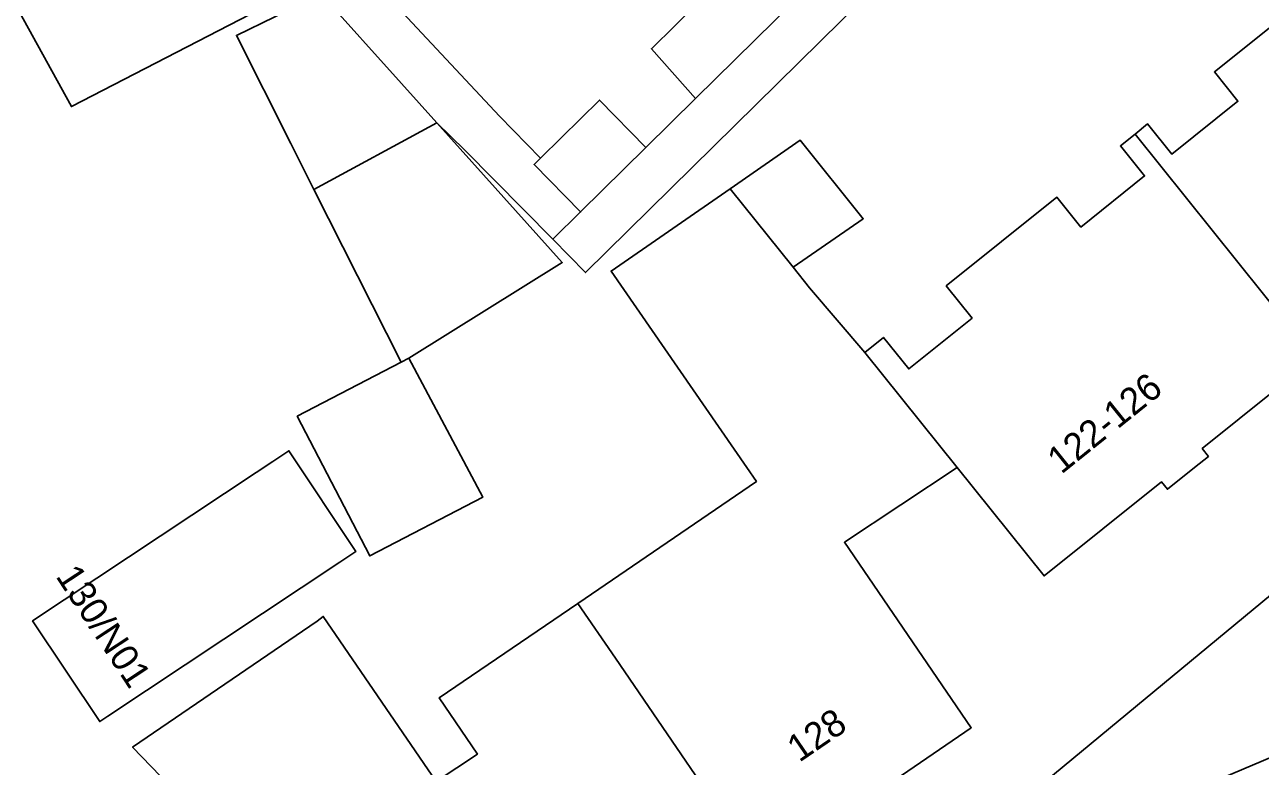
# Model space of a CAD drawing. Extents: x 161881 to 162523, y 381678 to 382381.
# Drawn here: x 162346.39 to 162392.21, y 381738.92 to 381766.42 of the extents above; entities that cross this region are included whole.
import ezdxf

# ---------------------------------------------------------------- set-up
doc = ezdxf.new("R2010")
doc.units = 0
for name, color, linetype in [('IMGEO_Erf', 7, 'Continuous'), ('IMGEO_Fietspad_gesloten', 7, 'Continuous'), ('IMGEO_Pand', 7, 'Continuous'), ('IMGEO_Pand_nummerreeks', 7, 'Continuous'), ('IMGEO_Voetpad_open', 7, 'Continuous')]:
    doc.layers.add(name, color=color, linetype=linetype)

msp = doc.modelspace()

# ---------------------------------------------------------------- linework, layer by layer
at = {"layer": 'IMGEO_Erf'}
for points in [[(162343.866, 381713.286), (162356.915, 381719.329), (162365.839, 381723.151), (162398.308, 381750), (162437.038, 381782.026)], [(162355.536, 381772.071), (162363.995, 381763.033), (162365.51, 381761.465), (162366.295, 381762.239), (162367.697, 381763.622), (162369.425, 381761.869), (162371.265, 381763.684), (162369.629, 381765.527), (162374.022, 381769.859)], [(162381.418, 381771.264), (162367.187, 381757.231), (162365.972, 381758.464), (162362.713, 381761.769), (162361.669, 381762.781), (162366.323, 381757.6), (162360.635, 381754.053), (162363.375, 381748.9), (162359.18, 381746.721), (162356.49, 381751.901), (162360.342, 381753.901), (162357.113, 381760.311), (162356.254, 381762.016), (162354.236, 381766.022), (162357.084, 381767.419)], [(162356.7, 381767.828), (162348.117, 381763.384), (162345.256, 381768.578)], [(162352.114, 381737.844), (162350.389, 381739.631), (162357.234, 381744.31), (162357.459, 381744.482), (162361.646, 381738.357), (162363.177, 381739.379), (162361.754, 381741.46), (162366.899, 381744.958), (162373.521, 381749.484), (162373.164, 381750), (162368.13, 381757.284), (162372.542, 381760.336), (162375.144, 381762.136), (162377.48, 381759.226), (162374.878, 381757.426), (162375.487, 381756.667), (162377.539, 381754.267), (162378.231, 381754.823), (162379.168, 381753.657), (162381.517, 381755.543), (162380.562, 381756.732), (162384.662, 381760.024), (162385.553, 381758.916), (162387.913, 381760.811), (162387.017, 381761.926), (162387.561, 381762.363), (162388.029, 381762.739), (162388.931, 381761.615), (162391.38, 381763.581), (162390.507, 381764.668), (162394.626, 381767.976)], [(162394.235, 381754.059), (162390.053, 381750.701), (162390.283, 381750.415), (162389.766, 381750), (162388.764, 381749.195), (162388.539, 381749.476), (162384.189, 381745.983), (162380.965, 381750), (162376.785, 381747.233), (162381.487, 381740.355), (162373.695, 381735.029)]]:
    msp.add_lwpolyline(points, dxfattribs=at)
msp.add_lwpolyline([(162358.664, 381746.886), (162358.069, 381746.491), (162349.473, 381740.786), (162349.167, 381740.583), (162346.677, 381744.311), (162354.964, 381749.81), (162355.59, 381750.226), (162356.111, 381750.571), (162356.185, 381750.621)], close=True, dxfattribs=at)
at = {"layer": 'IMGEO_Fietspad_gesloten'}
msp.add_lwpolyline([(162465.9, 381797.559), (162465.667, 381797.275), (162465.384, 381797.056), (162418.283, 381759.605), (162412.351, 381754.828), (162394.327, 381740.001), (162393.522, 381739.663), (162393.372, 381739.584), (162390.461, 381738.351), (162389.601, 381737.634), (162386.818, 381735.309), (162385.622, 381734.309), (162387.138, 381732.433), (162387.312, 381732.575), (162387.443, 381732.645), (162396.519, 381738.21), (162396.799, 381738.137), (162413.971, 381752.357), (162472.336, 381798.789)], dxfattribs=at)
at = {"layer": 'IMGEO_Pand'}
for points in [[(162356.7, 381767.828), (162352.533, 381772.272), (162345.256, 381768.578), (162348.117, 381763.384)], [(162404.147, 381762.016), (162397.503, 381770.285), (162397.027, 381769.903), (162397.869, 381768.855), (162395.468, 381766.928), (162394.626, 381767.976), (162390.507, 381764.668), (162391.38, 381763.581), (162388.931, 381761.615), (162388.029, 381762.739), (162387.561, 381762.363), (162394.235, 381754.059), (162398.417, 381757.417), (162398.654, 381757.121), (162400.207, 381758.367), (162399.97, 381758.662)], [(162369.629, 381765.527), (162371.265, 381763.684), (162375.677, 381768.034), (162374.022, 381769.859)], [(162360.358, 381764.241), (162357.375, 381767.562), (162357.084, 381767.419), (162354.236, 381766.022), (162356.254, 381762.016), (162357.113, 381760.311), (162361.669, 381762.781)], [(162367.697, 381763.622), (162366.295, 381762.239), (162365.51, 381761.465), (162365.275, 381761.233), (162367.003, 381759.48), (162369.425, 381761.869)], [(162361.669, 381762.781), (162357.113, 381760.311), (162360.342, 381753.901), (162360.635, 381754.053), (162366.323, 381757.6)], [(162372.542, 381760.336), (162374.878, 381757.426), (162377.48, 381759.226), (162375.144, 381762.136)], [(162377.539, 381754.267), (162380.965, 381750), (162384.189, 381745.983), (162388.539, 381749.476), (162388.764, 381749.195), (162389.766, 381750), (162390.283, 381750.415), (162390.053, 381750.701), (162394.235, 381754.059), (162387.561, 381762.363), (162387.017, 381761.926), (162387.913, 381760.811), (162385.553, 381758.916), (162384.662, 381760.024), (162380.562, 381756.732), (162381.517, 381755.543), (162379.168, 381753.657), (162378.231, 381754.823)], [(162380.965, 381750), (162377.539, 381754.267), (162375.487, 381756.667), (162374.878, 381757.426), (162372.542, 381760.336), (162368.13, 381757.284), (162373.164, 381750), (162373.521, 381749.484), (162366.899, 381744.958), (162368.297, 381742.927), (162373.695, 381735.029), (162381.487, 381740.355), (162376.785, 381747.233)], [(162360.635, 381754.053), (162360.342, 381753.901), (162356.49, 381751.901), (162359.18, 381746.721), (162363.375, 381748.9)], [(162346.677, 381744.311), (162349.167, 381740.583), (162349.473, 381740.786), (162358.069, 381746.491), (162358.664, 381746.886), (162356.185, 381750.621), (162356.111, 381750.571), (162355.59, 381750.226), (162354.964, 381749.81)], [(162368.297, 381742.927), (162366.899, 381744.958), (162361.754, 381741.46), (162363.177, 381739.379), (162361.646, 381738.357), (162357.459, 381744.482), (162357.234, 381744.31), (162350.389, 381739.631), (162352.114, 381737.844), (162355.587, 381734.247), (162358.085, 381735.973), (162357.709, 381736.522), (162360.101, 381738.157), (162360.503, 381737.607), (162365.905, 381729.703), (162373.695, 381735.029)]]:
    msp.add_lwpolyline(points, close=True, dxfattribs=at)
at = {"layer": 'IMGEO_Voetpad_open'}
for points in [[(162490.018, 381827.882), (162490.005, 381828.82), (162485.481, 381824.651), (162478.012, 381817.966), (162477.732, 381817.717), (162462.828, 381803.734), (162439.634, 381784.212), (162437.038, 381782.026), (162398.308, 381750), (162365.839, 381723.151), (162356.915, 381719.329), (162343.866, 381713.286), (162342.256, 381716.825), (162335.301, 381713.346), (162336.199, 381710.351)], [(162375.677, 381768.034), (162371.265, 381763.684), (162369.425, 381761.869), (162367.003, 381759.48), (162365.972, 381758.464), (162367.187, 381757.231), (162381.418, 381771.264)], [(162346.921, 381710.054), (162349.615, 381711.299), (162352.628, 381712.845), (162357.168, 381715.275), (162361.278, 381717.542), (162370.414, 381723.131), (162371.801, 381724.074), (162374.553, 381725.96), (162378.522, 381728.988), (162382.571, 381731.996), (162383.892, 381732.922), (162385.622, 381734.309), (162386.818, 381735.309), (162386.139, 381736.108), (162388.945, 381738.427), (162389.601, 381737.634), (162390.461, 381738.351), (162393.372, 381739.584), (162393.522, 381739.663)]]:
    msp.add_lwpolyline(points, dxfattribs=at)
msp.add_lwpolyline([(162355.536, 381772.071), (162352.98, 381774.802), (162349.562, 381778.452), (162346.786, 381781.417), (162345.044, 381780.258), (162352.533, 381772.272), (162356.7, 381767.828), (162357.084, 381767.419), (162357.375, 381767.562), (162360.358, 381764.241), (162361.669, 381762.781), (162362.713, 381761.769), (162365.972, 381758.464), (162367.003, 381759.48), (162365.275, 381761.233), (162365.51, 381761.465), (162363.995, 381763.033)], close=True, dxfattribs=at)

# ---------------------------------------------------------------- texts
at = {"layer": 'IMGEO_Pand_nummerreeks'}
for s, rotation, p in [('122-126', 38.7959, (162384.827, 381749.729)), ('130/N01', 303.3402, (162347.513, 381745.968)), ('128', 34.3545, (162375.109, 381739.048))]:
    msp.add_text(s, height=1, rotation=rotation, dxfattribs=at).set_placement(p)

doc.saveas('drawing.dxf')
